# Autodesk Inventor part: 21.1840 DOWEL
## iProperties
Created: 2007-05
Part Number: 21.1840 DOWEL
Material: Steel
Document SubType Name: Modeling
Designer: Andy Moles
Mass: 5.25701 g
Surface Area: 4.92597 cm^2
Volume: 0.669683 cm^3
Density: 7.85 g/cm^3
Author: Andy Moles
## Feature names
1. Extrusion1
2. Chamfer1
3. Chamfer2
